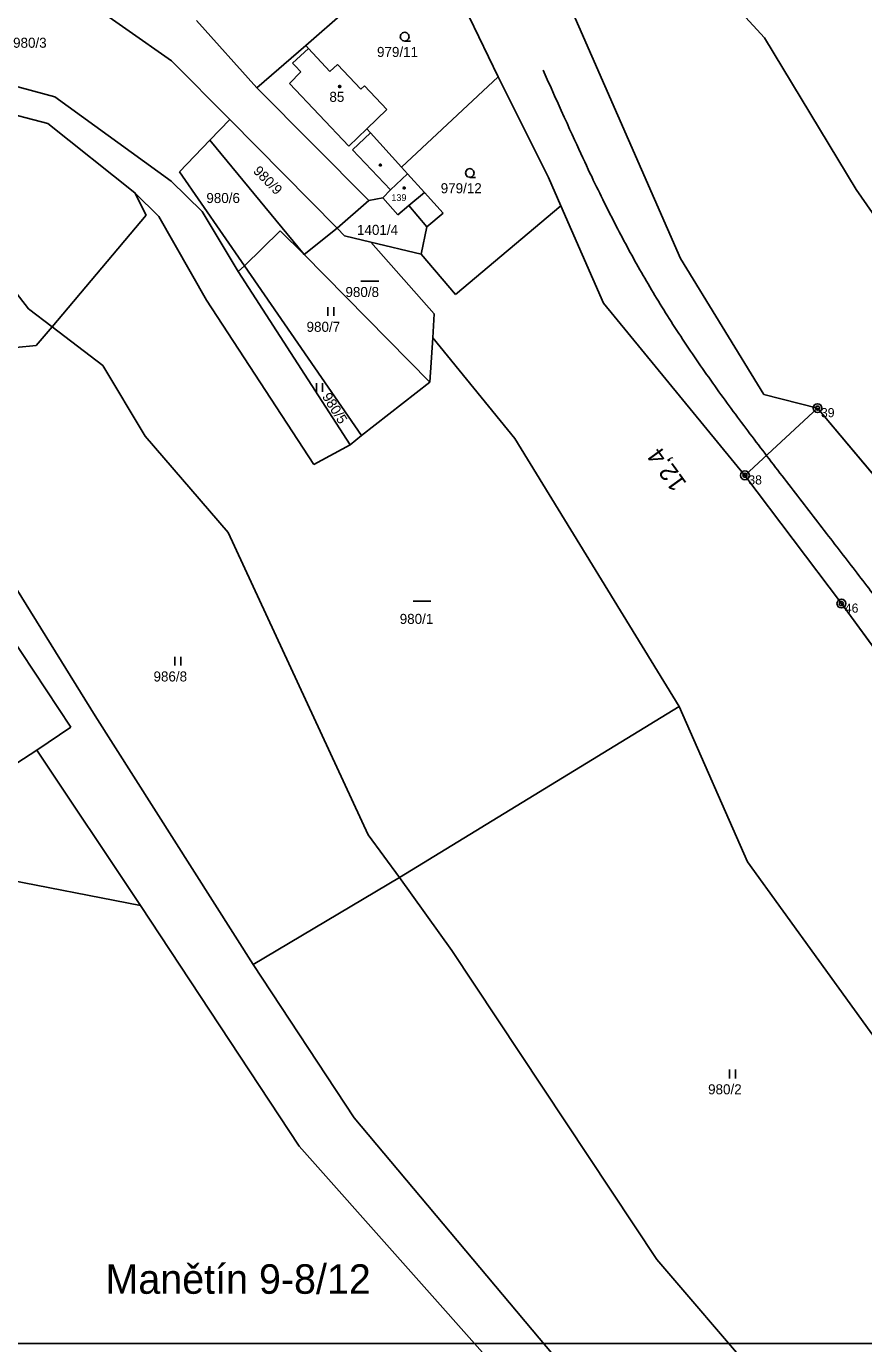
# Model space of a CAD drawing. Extents: x -852001 to -842497, y -1063614 to -1052182.
# Drawn here: x -849124.2 to -848982.2, y -1056500 to -1056276.7 of the extents above; entities that cross this region are included whole.
import ezdxf

# ---------------------------------------------------------------- set-up
doc = ezdxf.new("R2010")
doc.units = 0
for name, color, linetype in [('body', 7, 'Continuous'), ('cisla', 7, 'Continuous'), ('Default', 7, 'Continuous'), ('KLADY_ZMVM', 7, 'Continuous'), ('KN_HRANICE', 7, 'Continuous'), ('KN_KULTURY', 7, 'Continuous'), ('KN_PARCELY', 7, 'Continuous'), ('KN_SLUCKY', 7, 'Continuous'), ('obvod_stavby', 7, 'Continuous'), ('Vrstva 7', 7, 'Continuous'), ('Železniční svršek', 7, 'Continuous')]:
    doc.layers.add(name, color=color, linetype=linetype)

# ---------------------------------------------------------------- blocks, each defined once
blk = doc.blocks.new('304')
at = {"layer": 'Default'}
blk.add_lwpolyline([(0, 0), (-0.38, 0.1), (-0.65, 0.37), (-0.75, 0.74), (-0.65, 1.11), (-0.38, 1.38), (-0.01, 1.48), (0.36, 1.38), (0.63, 1.11), (0.73, 0.73), (0.63, 0.35), (0.36, 0.08), (-0.02, -0.02), (0.98, -0.02)], dxfattribs=at)
blk = doc.blocks.new('306')
at = {"layer": 'Default'}
for p, q in [((-0.5, 1.5), (-0.5, 0)), ((0.5, 0), (0.5, 1.5))]:
    blk.add_line(p, q, dxfattribs=at)
blk = doc.blocks.new('804')
at = {"layer": 'Default'}
blk.add_line((-1.5, 0), (1.5, 0), dxfattribs=at)
blk = doc.blocks.new('402')
at = {"layer": 'Default'}
blk.add_lwpolyline([(0.09, 0.15), (0.18, 0), (0.09, -0.15), (-0.09, -0.15), (-0.18, 0), (-0.09, 0.15), (0.09, 0.15)], dxfattribs=at)

msp = doc.modelspace()

# ---------------------------------------------------------------- linework, layer by layer
at = {"layer": 'body'}
for p, q in [((-848990.06, -1056341.42), (-848990.06, -1056341.42)), ((-849002.37, -1056352.82), (-849002.37, -1056352.82)), ((-848986.01, -1056374.55), (-848986.01, -1056374.55))]:
    msp.add_line(p, q, dxfattribs=at)
for centre, radius in [((-848990.06, -1056341.42), 0.75), ((-848990.06, -1056341.42), 0.35), ((-849002.37, -1056352.82), 0.75), ((-849002.37, -1056352.82), 0.35), ((-848986.01, -1056374.55), 0.75), ((-848986.01, -1056374.55), 0.35)]:
    msp.add_circle(centre, radius, dxfattribs=at)
at = {"layer": 'KLADY_ZMVM'}
msp.add_lwpolyline([(-849375, -1056500), (-848750, -1056500), (-848750, -1056000)], dxfattribs=at)
at = {"layer": 'KN_HRANICE'}
for p, q in [((-849132.64, -1056259.34), (-849099.56, -1056282.53)), ((-849132.64, -1056259.34), (-849099.56, -1056282.53)), ((-849016.97, -1056259.04), (-848999.06, -1056278.65)), ((-849016.97, -1056259.04), (-848999.06, -1056278.65)), ((-849044.22, -1056285.28), (-849055.56, -1056261.61)), ((-849044.22, -1056285.28), (-849055.56, -1056261.61)), ((-849034.65, -1056267.35), (-849013.3, -1056316.04)), ((-849034.65, -1056267.35), (-849013.3, -1056316.04)), ((-849070.1, -1056274.09), (-849076.82, -1056279.93)), ((-849070.1, -1056274.09), (-849076.82, -1056279.93)), ((-849085.1, -1056287.14), (-849095.37, -1056275.7)), ((-849085.1, -1056287.14), (-849095.37, -1056275.7)), ((-848983.5, -1056304.39), (-848999.06, -1056278.65)), ((-848983.5, -1056304.39), (-848999.06, -1056278.65)), ((-849076.82, -1056279.93), (-849085.1, -1056287.14)), ((-849076.82, -1056279.93), (-849085.1, -1056287.14)), ((-849076.82, -1056279.93), (-849076.38, -1056280.44)), ((-849076.82, -1056279.93), (-849076.38, -1056280.44)), ((-849076.38, -1056280.44), (-849072.72, -1056284.35)), ((-849076.38, -1056280.44), (-849072.72, -1056284.35)), ((-849099.56, -1056282.53), (-849089.69, -1056292.52)), ((-849099.56, -1056282.53), (-849089.69, -1056292.52)), ((-849072.72, -1056284.35), (-849071.45, -1056283.16)), ((-849072.72, -1056284.35), (-849071.45, -1056283.16)), ((-849071.45, -1056283.16), (-849067.51, -1056287.35)), ((-849071.45, -1056283.16), (-849067.51, -1056287.35)), ((-849119.35, -1056288.63), (-849134.31, -1056284.69)), ((-849119.35, -1056288.63), (-849134.31, -1056284.69)), ((-849060.61, -1056300.57), (-849044.22, -1056285.28)), ((-849060.61, -1056300.57), (-849044.22, -1056285.28)), ((-849035.65, -1056302.35), (-849044.22, -1056285.28)), ((-849035.65, -1056302.35), (-849044.22, -1056285.28)), ((-849085.1, -1056287.14), (-849066.14, -1056306.21)), ((-849085.1, -1056287.14), (-849066.14, -1056306.21)), ((-849067.51, -1056287.35), (-849066.89, -1056286.77)), ((-849067.51, -1056287.35), (-849066.89, -1056286.77)), ((-849066.89, -1056286.77), (-849063.1, -1056290.8)), ((-849066.89, -1056286.77), (-849063.1, -1056290.8)), ((-849135.51, -1056289.24), (-849120.55, -1056293.17)), ((-849135.51, -1056289.24), (-849120.55, -1056293.17)), ((-849119.35, -1056288.63), (-849099.62, -1056302.96)), ((-849119.35, -1056288.63), (-849099.62, -1056302.96)), ((-849093.06, -1056296.02), (-849089.69, -1056292.52)), ((-849093.06, -1056296.02), (-849089.69, -1056292.52)), ((-849089.69, -1056292.52), (-849071.52, -1056310.9)), ((-849089.69, -1056292.52), (-849071.52, -1056310.9)), ((-849063.1, -1056290.8), (-849066.44, -1056294.11)), ((-849063.1, -1056290.8), (-849066.44, -1056294.11)), ((-849123.81, -1056324.58), (-849147.96, -1056293.59)), ((-849123.81, -1056324.58), (-849147.96, -1056293.59)), ((-849120.55, -1056293.17), (-849105.79, -1056304.92)), ((-849120.55, -1056293.17), (-849105.79, -1056304.92)), ((-849065.87, -1056294.74), (-849066.44, -1056294.11)), ((-849065.87, -1056294.74), (-849066.44, -1056294.11)), ((-849060.61, -1056300.57), (-849065.87, -1056294.74)), ((-849060.61, -1056300.57), (-849065.87, -1056294.74)), ((-849098.21, -1056301.36), (-849093.06, -1056296.02)), ((-849098.21, -1056301.36), (-849093.06, -1056296.02)), ((-849093.06, -1056296.02), (-849077.08, -1056315.37)), ((-849093.06, -1056296.02), (-849077.08, -1056315.37)), ((-849087.23, -1056317.3), (-849098.21, -1056301.36)), ((-849087.23, -1056317.3), (-849098.21, -1056301.36)), ((-849059.57, -1056301.72), (-849060.61, -1056300.57)), ((-849059.57, -1056301.72), (-849060.61, -1056300.57)), ((-849099.62, -1056302.96), (-849094.39, -1056308.08)), ((-849099.62, -1056302.96), (-849094.39, -1056308.08)), ((-849062.46, -1056304.42), (-849059.57, -1056301.72)), ((-849062.46, -1056304.42), (-849059.57, -1056301.72)), ((-849056.7, -1056304.89), (-849059.57, -1056301.72)), ((-849056.7, -1056304.89), (-849059.57, -1056301.72)), ((-849033.57, -1056307.12), (-849035.65, -1056302.35)), ((-849033.57, -1056307.12), (-849035.65, -1056302.35)), ((-849103.9, -1056308.71), (-849105.79, -1056304.92)), ((-849105.79, -1056304.92), (-849101.71, -1056308.92)), ((-849103.9, -1056308.71), (-849105.79, -1056304.92)), ((-849105.79, -1056304.92), (-849101.71, -1056308.92)), ((-849066.14, -1056306.21), (-849063.74, -1056305.76)), ((-849066.14, -1056306.21), (-849063.74, -1056305.76)), ((-849063.74, -1056305.76), (-849062.46, -1056304.42)), ((-849063.74, -1056305.76), (-849062.46, -1056304.42)), ((-849063.74, -1056305.76), (-849061.22, -1056308.64)), ((-849063.74, -1056305.76), (-849061.22, -1056308.64)), ((-849053.54, -1056308.4), (-849056.7, -1056304.89)), ((-849053.54, -1056308.4), (-849056.7, -1056304.89)), ((-848967.17, -1056327.9), (-848983.5, -1056304.39)), ((-848967.17, -1056327.9), (-848983.5, -1056304.39)), ((-849094.39, -1056308.08), (-849088.27, -1056318.26)), ((-849094.39, -1056308.08), (-849088.27, -1056318.26)), ((-849066.14, -1056306.21), (-849071.52, -1056310.9)), ((-849066.14, -1056306.21), (-849071.52, -1056310.9)), ((-849061.22, -1056308.64), (-849059.32, -1056307.07)), ((-849061.22, -1056308.64), (-849059.32, -1056307.07)), ((-849059.32, -1056307.07), (-849056.31, -1056310.7)), ((-849059.32, -1056307.07), (-849056.31, -1056310.7)), ((-849051.42, -1056322.16), (-849033.57, -1056307.12)), ((-849051.42, -1056322.16), (-849033.57, -1056307.12)), ((-849026.35, -1056323.66), (-849033.57, -1056307.12)), ((-849026.35, -1056323.66), (-849033.57, -1056307.12)), ((-849119.84, -1056327.63), (-849103.9, -1056308.71)), ((-849119.84, -1056327.63), (-849103.9, -1056308.71)), ((-849101.71, -1056308.92), (-849093.63, -1056323.1)), ((-849101.71, -1056308.92), (-849093.63, -1056323.1)), ((-849056.31, -1056310.7), (-849053.54, -1056308.4)), ((-849056.31, -1056310.7), (-849053.54, -1056308.4)), ((-849081.17, -1056311.38), (-849087.23, -1056317.3)), ((-849081.17, -1056311.38), (-849087.23, -1056317.3)), ((-849077.08, -1056315.37), (-849081.17, -1056311.38)), ((-849077.08, -1056315.37), (-849081.17, -1056311.38)), ((-849077.08, -1056315.37), (-849071.52, -1056310.9)), ((-849077.08, -1056315.37), (-849071.52, -1056310.9)), ((-849071.52, -1056310.9), (-849070.27, -1056312.21)), ((-849071.52, -1056310.9), (-849070.27, -1056312.21)), ((-849065.77, -1056313.28), (-849070.27, -1056312.21)), ((-849065.77, -1056313.28), (-849070.27, -1056312.21)), ((-849056.31, -1056310.7), (-849057.24, -1056315.32)), ((-849056.31, -1056310.7), (-849057.24, -1056315.32)), ((-849057.24, -1056315.32), (-849065.77, -1056313.28)), ((-849065.77, -1056313.28), (-849055.03, -1056325.42)), ((-849057.24, -1056315.32), (-849065.77, -1056313.28)), ((-849065.77, -1056313.28), (-849055.03, -1056325.42)), ((-849077.08, -1056315.37), (-849055.79, -1056337.03)), ((-849077.08, -1056315.37), (-849055.79, -1056337.03)), ((-849057.24, -1056315.32), (-849051.42, -1056322.16)), ((-849057.24, -1056315.32), (-849051.42, -1056322.16)), ((-849013.3, -1056316.04), (-848999.16, -1056339.1)), ((-849013.3, -1056316.04), (-848999.16, -1056339.1)), ((-849088.27, -1056318.26), (-849087.23, -1056317.3)), ((-849088.27, -1056318.26), (-849087.23, -1056317.3)), ((-849069.32, -1056347.66), (-849088.27, -1056318.26)), ((-849069.32, -1056347.66), (-849088.27, -1056318.26)), ((-849067.39, -1056346.09), (-849087.23, -1056317.3)), ((-849067.39, -1056346.09), (-849087.23, -1056317.3)), ((-849093.63, -1056323.1), (-849075.46, -1056350.96)), ((-849093.63, -1056323.1), (-849075.46, -1056350.96)), ((-849002.37, -1056352.82), (-849026.35, -1056323.66)), ((-849002.37, -1056352.82), (-849026.35, -1056323.66)), ((-849123.81, -1056324.58), (-849119.84, -1056327.63)), ((-849123.81, -1056324.58), (-849119.84, -1056327.63)), ((-849055.3, -1056329.49), (-849055.03, -1056325.42)), ((-849055.3, -1056329.49), (-849055.03, -1056325.42)), ((-849122.51, -1056330.8), (-849119.84, -1056327.63)), ((-849122.51, -1056330.8), (-849119.84, -1056327.63)), ((-849119.84, -1056327.63), (-849111.2, -1056334.22)), ((-849119.84, -1056327.63), (-849111.2, -1056334.22)), ((-849055.79, -1056337.03), (-849055.3, -1056329.49)), ((-849055.79, -1056337.03), (-849055.3, -1056329.49)), ((-849041.37, -1056346.6), (-849055.3, -1056329.49)), ((-849041.37, -1056346.6), (-849055.3, -1056329.49)), ((-849125.99, -1056331.15), (-849122.51, -1056330.8)), ((-849125.99, -1056331.15), (-849122.51, -1056330.8)), ((-849104.06, -1056346.16), (-849111.2, -1056334.22)), ((-849104.06, -1056346.16), (-849111.2, -1056334.22)), ((-849067.39, -1056346.09), (-849055.79, -1056337.03)), ((-849067.39, -1056346.09), (-849055.79, -1056337.03)), ((-848999.16, -1056339.1), (-848990.06, -1056341.42)), ((-848999.16, -1056339.1), (-848990.06, -1056341.42)), ((-848990.06, -1056341.42), (-848946.95, -1056392.82)), ((-848990.06, -1056341.42), (-848946.95, -1056392.82)), ((-849069.32, -1056347.66), (-849067.39, -1056346.09)), ((-849069.32, -1056347.66), (-849067.39, -1056346.09)), ((-849089.97, -1056362.5), (-849104.06, -1056346.16)), ((-849089.97, -1056362.5), (-849104.06, -1056346.16)), ((-849075.46, -1056350.96), (-849069.32, -1056347.66)), ((-849075.46, -1056350.96), (-849069.32, -1056347.66)), ((-849013.53, -1056391.99), (-849041.37, -1056346.6)), ((-849013.53, -1056391.99), (-849041.37, -1056346.6)), ((-849112.51, -1056393.58), (-849139.79, -1056349.71)), ((-849112.51, -1056393.58), (-849139.79, -1056349.71)), ((-848986.01, -1056374.55), (-849002.37, -1056352.82)), ((-848986.01, -1056374.55), (-849002.37, -1056352.82)), ((-849116.66, -1056395.53), (-849141.27, -1056358.26)), ((-849116.66, -1056395.53), (-849141.27, -1056358.26)), ((-849089.97, -1056362.5), (-849066.26, -1056413.75)), ((-849089.97, -1056362.5), (-849066.26, -1056413.75)), ((-848960.15, -1056409.91), (-848986.01, -1056374.55)), ((-848960.15, -1056409.91), (-848986.01, -1056374.55)), ((-849060.94, -1056420.96), (-849013.53, -1056391.99)), ((-849060.94, -1056420.96), (-849013.53, -1056391.99)), ((-849013.53, -1056391.99), (-849001.93, -1056418.36)), ((-849013.53, -1056391.99), (-849001.93, -1056418.36)), ((-849085.71, -1056435.76), (-849112.51, -1056393.58)), ((-849085.71, -1056435.76), (-849112.51, -1056393.58)), ((-849122.42, -1056399.43), (-849116.66, -1056395.53)), ((-849122.42, -1056399.43), (-849116.66, -1056395.53)), ((-849153.92, -1056419.76), (-849122.42, -1056399.43)), ((-849153.92, -1056419.76), (-849122.42, -1056399.43)), ((-849104.83, -1056425.71), (-849122.42, -1056399.43)), ((-849104.83, -1056425.71), (-849122.42, -1056399.43)), ((-849066.26, -1056413.75), (-849060.94, -1056420.96)), ((-849066.26, -1056413.75), (-849060.94, -1056420.96)), ((-849139.78, -1056418.98), (-849104.83, -1056425.71)), ((-849139.78, -1056418.98), (-849104.83, -1056425.71)), ((-849001.93, -1056418.36), (-848977.76, -1056451.81)), ((-849001.93, -1056418.36), (-848977.76, -1056451.81)), ((-849085.71, -1056435.76), (-849060.94, -1056420.96)), ((-849085.71, -1056435.76), (-849060.94, -1056420.96)), ((-849052.06, -1056433.36), (-849060.94, -1056420.96)), ((-849052.06, -1056433.36), (-849060.94, -1056420.96)), ((-849104.83, -1056425.71), (-849077.96, -1056466.55)), ((-849104.83, -1056425.71), (-849077.96, -1056466.55)), ((-849017.3, -1056485.72), (-849052.06, -1056433.36)), ((-849017.3, -1056485.72), (-849052.06, -1056433.36)), ((-849068.63, -1056461.72), (-849085.71, -1056435.76)), ((-849068.63, -1056461.72), (-849085.71, -1056435.76)), ((-849017.61, -1056522.4), (-849068.63, -1056461.72)), ((-849017.61, -1056522.4), (-849068.63, -1056461.72)), ((-849077.96, -1056466.55), (-849036.41, -1056513.21)), ((-849077.96, -1056466.55), (-849036.41, -1056513.21)), ((-848985.11, -1056523.29), (-849017.3, -1056485.72)), ((-848985.11, -1056523.29), (-849017.3, -1056485.72))]:
    msp.add_line(p, q, dxfattribs=at)
at = {"layer": 'KN_SLUCKY'}
for p, q in [((-849079.06, -1056282.95), (-849076.38, -1056280.44)), ((-849079.06, -1056282.95), (-849076.38, -1056280.44)), ((-849078.61, -1056283.42), (-849079.06, -1056282.95)), ((-849078.61, -1056283.42), (-849079.06, -1056282.95)), ((-849077.65, -1056284.44), (-849078.61, -1056283.42)), ((-849077.65, -1056284.44), (-849078.61, -1056283.42)), ((-849079.55, -1056286.37), (-849077.65, -1056284.44)), ((-849079.55, -1056286.37), (-849077.65, -1056284.44)), ((-849069.52, -1056297.01), (-849079.55, -1056286.37)), ((-849069.52, -1056297.01), (-849079.55, -1056286.37)), ((-849066.44, -1056294.11), (-849069.52, -1056297.01)), ((-849066.44, -1056294.11), (-849069.52, -1056297.01)), ((-849068.9, -1056297.62), (-849065.87, -1056294.74)), ((-849068.9, -1056297.62), (-849065.87, -1056294.74)), ((-849062.46, -1056304.42), (-849068.9, -1056297.62)), ((-849062.46, -1056304.42), (-849068.9, -1056297.62)), ((-849059.32, -1056307.07), (-849056.7, -1056304.89)), ((-849059.32, -1056307.07), (-849056.7, -1056304.89))]:
    msp.add_line(p, q, dxfattribs=at)
at = {"layer": 'obvod_stavby'}
for points in [[(-848936.28, -1056450.22), (-848946.06, -1056425.85), (-848960.15, -1056409.91), (-848986.01, -1056374.55), (-849002.37, -1056352.82), (-848990.06, -1056341.42)], [(-848919.27, -1056437.97), (-848935.25, -1056424.04), (-848946.95, -1056392.82), (-848990.06, -1056341.42)]]:
    msp.add_lwpolyline(points, dxfattribs=at)
at = {"layer": 'Železniční svršek'}
msp.add_open_spline([(-848892.81, -1056486.91), (-848898.96, -1056478.95), (-848904.39, -1056471.91), (-848910.36, -1056464.18), (-848915.68, -1056457.29), (-848922.02, -1056449.05), (-848928.2, -1056441.01), (-848934.22, -1056433.18), (-848940.17, -1056425.45), (-848946.67, -1056417), (-848952.25, -1056409.77), (-848955.57, -1056405.45), (-848960.77, -1056398.71), (-848966.2, -1056391.67), (-848971.61, -1056384.64), (-848977.18, -1056377.42), (-848982.34, -1056370.71), (-848987.69, -1056363.77), (-848993.84, -1056355.79), (-848999.77, -1056348.09), (-849005.4, -1056340.62), (-849010.95, -1056332.79), (-849016.27, -1056324.7), (-849020.78, -1056317.03), (-849025.01, -1056309.08), (-849028.91, -1056301.1), (-849032.78, -1056292.63), (-849036.57, -1056284.16)], degree=3, dxfattribs=at)

# ---------------------------------------------------------------- block references
at = {"layer": 'KN_KULTURY'}
for name, p in [('304', (-849060.04, -1056279.2)), ('304', (-849060.04, -1056279.2)), ('402', (-849071.07, -1056286.9)), ('402', (-849071.07, -1056286.9)), ('402', (-849064.17, -1056300.21)), ('402', (-849064.17, -1056300.21)), ('304', (-849049, -1056302.3)), ('304', (-849049, -1056302.3)), ('402', (-849060.14, -1056304.1)), ('402', (-849060.14, -1056304.1)), ('804', (-849065.96, -1056319.89)), ('804', (-849065.96, -1056319.89)), ('306', (-849072.55, -1056325.79)), ('306', (-849072.55, -1056325.79)), ('306', (-849074.49, -1056338.69)), ('306', (-849074.49, -1056338.69)), ('804', (-849057.13, -1056374.15)), ('804', (-849057.13, -1056374.15)), ('306', (-849098.5, -1056385.06)), ('306', (-849098.5, -1056385.06)), ('306', (-849004.48, -1056455.04)), ('306', (-849004.48, -1056455.04))]:
    msp.add_blockref(name, p, dxfattribs=at)

# ---------------------------------------------------------------- texts
at = {"layer": 'cisla'}
for s, p in [(' 39', (-848990.06, -1056342.97)), (' 38', (-849002.37, -1056354.37)), (' 46', (-848986.01, -1056376.1))]:
    msp.add_text(s, height=1.552, dxfattribs=at).set_placement(p)
at = {"layer": 'KLADY_ZMVM'}
msp.add_text('Manětín 9-8/12', height=5, dxfattribs=at).set_placement((-849110.77, -1056491.55))
at = {"layer": 'KN_PARCELY'}
for s, height, p in [('980/3', 1.7, (-849126.44, -1056280.34)), ('980/3', 1.7, (-849126.44, -1056280.34)), ('979/11', 1.7, (-849064.74, -1056281.9)), ('979/11', 1.7, (-849064.74, -1056281.9)), ('85', 1.7, (-849072.81, -1056289.51)), ('85', 1.7, (-849072.81, -1056289.51)), ('979/12', 1.7, (-849053.94, -1056305)), ('979/12', 1.7, (-849053.94, -1056305)), ('980/6', 1.7, (-849093.67, -1056306.66)), ('980/6', 1.7, (-849093.67, -1056306.66)), ('139', 1.14, (-849062.3, -1056306.31)), ('139', 1.14, (-849062.3, -1056306.31)), ('1401/4', 1.7, (-849068.13, -1056312.06)), ('1401/4', 1.7, (-849068.13, -1056312.06)), ('980/8', 1.7, (-849070.09, -1056322.59)), ('980/8', 1.7, (-849070.09, -1056322.59)), ('980/7', 1.7, (-849076.68, -1056328.49)), ('980/7', 1.7, (-849076.68, -1056328.49)), ('980/1', 1.7, (-849060.89, -1056378)), ('980/1', 1.7, (-849060.89, -1056378)), ('986/8', 1.7, (-849102.63, -1056387.76)), ('986/8', 1.7, (-849102.63, -1056387.76)), ('980/2', 1.7, (-849008.61, -1056457.74)), ('980/2', 1.7, (-849008.61, -1056457.74))]:
    msp.add_text(s, height=height, dxfattribs=at).set_placement(p)
for s, rotation, p in [('980/9', 314.783, (-849085.85, -1056301.37)), ('980/9', 314.783, (-849085.85, -1056301.37)), ('980/5', 302.121, (-849074.12, -1056339.47)), ('980/5', 302.121, (-849074.12, -1056339.47))]:
    msp.add_text(s, height=1.7, rotation=rotation, dxfattribs=at).set_placement(p)
at = {"layer": 'Vrstva 7'}
msp.add_text('12,4', height=3, rotation=125.7923, dxfattribs=at).set_placement((-849012.14, -1056354.16))

doc.saveas('drawing.dxf')
